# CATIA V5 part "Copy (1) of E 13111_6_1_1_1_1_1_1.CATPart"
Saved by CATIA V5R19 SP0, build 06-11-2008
Part number: Copy (1) of E 13111_6_1_1_1_1_1_1
Definition: E 13111_6
Nomenclature: E 13111_6
Source: Unknown
Description: PART-E 13111_6-DESC
Bounding box of the stored display mesh (mm): x -3 to 3, y -3 to 3, z -26 to -8
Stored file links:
  C:\Users\jsmid\Desktop\DP_Smidak_Forma LEGO\Copy (1) of E 13111_6_1_1_1_1_1_1.CATPart
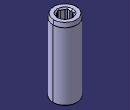
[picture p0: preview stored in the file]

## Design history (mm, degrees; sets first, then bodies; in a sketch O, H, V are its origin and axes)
Body1 "E 13111_6" (main body)
  Solid1: solid without history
